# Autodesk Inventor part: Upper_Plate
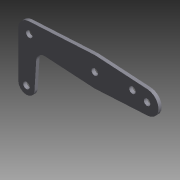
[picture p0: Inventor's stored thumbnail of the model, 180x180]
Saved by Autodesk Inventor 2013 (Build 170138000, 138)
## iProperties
Shininess: 15.0
Length Units: 11272
Angle Units: 11279
Time Units: 11290
Mass Units: 11283
Length Display Precision: 2
Angle Display Precision: 1
Compacted: True
Created: 1999-05
Part Number: Upper_Plate
Document SubType Name: Modeling
Designer: Administrator
Density: 7.86 g/cm^3
Material: Steel, Mild
Density: 7.86
Volumn: 11.910644871161018
Area: 90.04134983224549
PropertySet Name: Model Information
Control State: 0
Master: False
Checked Out: False
Author: Administrator
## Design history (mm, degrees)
node "y-z Plane"
  node "x-z Plane"
  node "x-y Plane"
node "Extrusion1" dims "d10" = 3.175, "d11" = 0
  sketch "Sketch1"
    geometry: L1 (-74.168, -44.756)-(-74.168, -0.306); L2 (-64.097, 10.346)-(-0.797, 13.896); L3 (0.882, 13.891)-(51.487, 10.747); L4 (51.42, -11.362)-(0.797, -14.202); L5 (-0.882, -14.197)-(-48.27, -11.253); L6 (-56.791, -18.777)-(-58.435, -45.244); L7 (0, 27.279)-(0, -66.228) reference; L8 (-103.926, 0)-(89.546, 0) reference; A1 r 10.668 centre (-63.5, -0.306) between (-64.097, 10.346) and (-74.168, -0.306); A2 r 11.074 centre (50.8, -0.306) between (51.42, -11.362) and (51.487, 10.747); A3 r 8.038 centre (-48.768, -19.275) between (-48.27, -11.253) and (-56.791, -18.777); A4 r 7.874 centre (-66.294, -44.756) between (-74.168, -44.756) and (-58.435, -45.244); A5 r 14.224 centre (0, -0.306) between (0.882, 13.891) and (-0.797, 13.896); A6 r 14.224 centre (0, 0) between (-0.882, -14.197) and (0.797, -14.202); 1 further point
    constraints: 12 end point, 12 point on circle, 12 tangent, 6 centre point, 2 horizontal alignment, 2 parallel, 1 coincident, 1 equal radius, 1 perpendicular, 1 vertical, 1 vertical alignment
    dimensions: "d0" = 14.224 radius of A5; "d1" = 10.668 radius of A1; "d2" = 18.96975 vertical distance of A3.centre A1.centre; "d3" = 7.874 radius of A4; "d4" = 44.45 vertical distance of A1.centre A4.centre; "d5" = 17.526 horizontal distance of A3.centre A4.centre; "d8" = 63.5 distance of A1.centre A5.centre; "d9" = 114.3 distance of A2.centre A1.centre
node "Hole1" dims "d14" = 6.35, "d15" = 9.525, "d16" = 6.35, "d17" = 60 deg, "d18" = 19.05, "d19" = 118 deg
  sketch "Sketch2"
    geometry: A1 r 7.874 centre (-66.294, -44.756) between (-74.168, -44.756) and (-58.435, -45.244) reference; A2 r 11.074 centre (50.8, -0.306) between (51.42, -11.362) and (51.487, 10.747) reference; A3 r 14.224 centre (0, -0.306) between (0.882, 13.891) and (-0.797, 13.896) reference; A4 r 10.668 centre (-63.5, -0.306) between (-64.097, 10.346) and (-74.168, -0.306) reference; 1 further point
    dimensions: "d12" = 36.576 horizontal distance of A3.centre point (36.576, 2.742); "d13" = 3.048 vertical distance of A3.centre point (36.576, 2.742)
body "Solid1"
